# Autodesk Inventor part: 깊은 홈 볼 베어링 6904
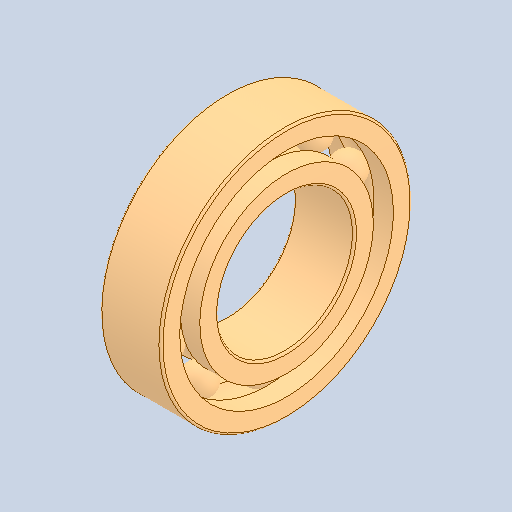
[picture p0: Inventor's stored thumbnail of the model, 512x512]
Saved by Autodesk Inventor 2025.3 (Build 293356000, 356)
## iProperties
Created: 2025-09
Part Number: 깊은 홈 볼 베어링 6904
Material: 강철, 연강
Description: 깊은 그루브 볼 베어링
Document SubType Name: Modeling
Designer: PC-15
Density: 7.85 g/cm^3
Appearance: 기본값
Author: jhkim
Sending System: Autodesk Inventor 2026
Preprocessor: ST-DEVELOPER v20.1
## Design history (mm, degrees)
feature "Solid1"
feature "Solid1:1"
feature "Solid1:2"
feature "Solid1:3"
feature "Solid1:4"
feature "Solid1:5"
feature "Solid1:6"
feature "Solid1:7"
feature "Solid1:8"
feature "Solid1:9"
feature "Solid1:10"
feature "Solid1:11"
node "솔리드1"
node "솔리드2"
node "솔리드3"
node "솔리드4"
node "솔리드5"
node "솔리드6"
node "솔리드7"
node "솔리드8"
node "솔리드9"
node "솔리드10"
node "솔리드11"
node "솔리드12"
